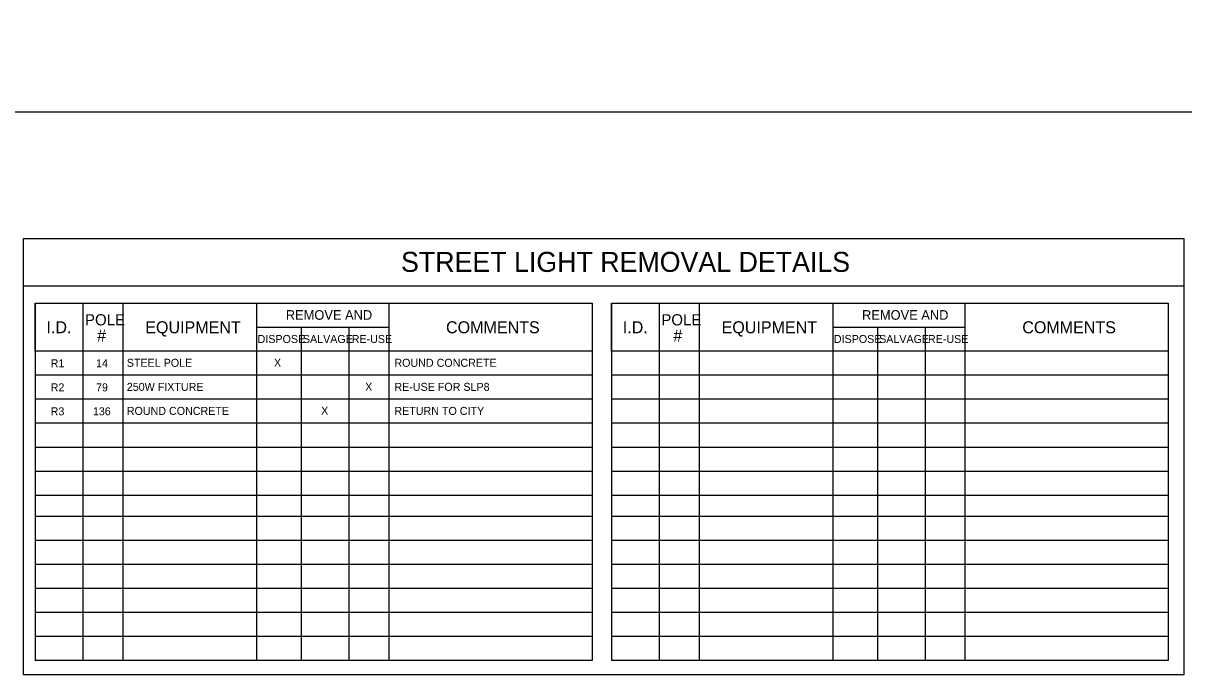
# Model space of a CAD drawing. Extents: x 602909 to 603631, y 4846273 to 4846729.
# Drawn here: x 603054.8 to 603194.8, y 4846272.8 to 4846351.3 of the extents above; entities that cross this region are included whole.
import ezdxf

# ---------------------------------------------------------------- set-up
doc = ezdxf.new("R2010")
doc.units = 0
for name, color, linetype in [('-PRINT FULLSIZE', 7, 'Continuous'), ('ENG_BORDER', 7, 'Continuous'), ('ENG_TITLEBLOCK', 7, 'Continuous'), ('ENG_TX_TITLEBLOCK', 7, 'Continuous'), ('SL - Border Text', 7, 'Continuous')]:
    doc.layers.add(name, color=color, linetype=linetype)

msp = doc.modelspace()

# ---------------------------------------------------------------- linework, layer by layer
at = {"layer": '-PRINT FULLSIZE'}
msp.add_lwpolyline([(602930, 4846340.65), (603377.03, 4846340.65), (603377.03, 4846645.65), (602930, 4846645.65)], close=True, dxfattribs=at)
at = {"layer": 'ENG_BORDER'}
msp.add_line((603054.8, 4846319.66), (603194.76, 4846319.66), dxfattribs=at)
msp.add_lwpolyline([(603054.8, 4846325.39), (603194.76, 4846325.39), (603194.76, 4846272.8), (603054.8, 4846272.8)], close=True, dxfattribs=at)
at = {"layer": 'ENG_TITLEBLOCK'}
for p, q in [((603056.19, 4846317.59), (603056.19, 4846274.5)), ((603061.96, 4846317.59), (603061.96, 4846274.5)), ((603066.79, 4846317.59), (603066.79, 4846274.5)), ((603082.92, 4846317.59), (603082.92, 4846274.5)), ((603098.85, 4846317.59), (603098.85, 4846274.5)), ((603123.38, 4846317.59), (603123.38, 4846274.5)), ((603125.71, 4846317.59), (603125.71, 4846274.5)), ((603131.47, 4846317.59), (603131.47, 4846274.5)), ((603136.31, 4846317.59), (603136.31, 4846274.5)), ((603152.43, 4846317.59), (603152.43, 4846274.5)), ((603168.36, 4846317.59), (603168.36, 4846274.5)), ((603192.89, 4846317.59), (603192.89, 4846274.5)), ((603082.92, 4846314.7), (603098.85, 4846314.7)), ((603088.31, 4846314.7), (603088.31, 4846274.5)), ((603094.05, 4846314.7), (603094.05, 4846274.5)), ((603152.43, 4846314.7), (603168.36, 4846314.7)), ((603157.82, 4846314.7), (603157.82, 4846274.5)), ((603163.56, 4846314.7), (603163.56, 4846274.5)), ((603123.38, 4846308.9), (603056.19, 4846308.9)), ((603192.89, 4846308.9), (603125.71, 4846308.9)), ((603123.38, 4846306.01), (603056.19, 4846306.01)), ((603192.89, 4846306.01), (603125.71, 4846306.01)), ((603123.38, 4846303.11), (603056.19, 4846303.11)), ((603192.89, 4846303.11), (603125.71, 4846303.11)), ((603123.38, 4846300.21), (603056.19, 4846300.21)), ((603192.89, 4846300.21), (603125.71, 4846300.21)), ((603123.38, 4846297.32), (603056.19, 4846297.32)), ((603192.89, 4846297.32), (603125.71, 4846297.32)), ((603123.38, 4846294.42), (603056.19, 4846294.42)), ((603192.89, 4846294.42), (603125.71, 4846294.42)), ((603123.38, 4846291.88), (603056.19, 4846291.88)), ((603192.89, 4846291.88), (603125.71, 4846291.88)), ((603123.38, 4846288.98), (603056.19, 4846288.98)), ((603192.89, 4846288.98), (603125.71, 4846288.98)), ((603123.38, 4846286.09), (603056.19, 4846286.09)), ((603192.89, 4846286.09), (603125.71, 4846286.09)), ((603123.38, 4846283.19), (603056.19, 4846283.19)), ((603192.89, 4846283.19), (603125.71, 4846283.19)), ((603123.38, 4846280.29), (603056.19, 4846280.29)), ((603192.89, 4846280.29), (603125.71, 4846280.29)), ((603123.38, 4846277.4), (603056.19, 4846277.4)), ((603192.89, 4846277.4), (603125.71, 4846277.4)), ((603123.38, 4846274.5), (603056.19, 4846274.5)), ((603192.89, 4846274.5), (603125.71, 4846274.5))]:
    msp.add_line(p, q, dxfattribs=at)
for points in [[(603056.19, 4846317.59), (603123.38, 4846317.59), (603123.38, 4846311.8), (603056.19, 4846311.8)], [(603125.71, 4846317.59), (603192.89, 4846317.59), (603192.89, 4846311.8), (603125.71, 4846311.8)]]:
    msp.add_lwpolyline(points, close=True, dxfattribs=at)
at = {"layer": 'SL - Border Text'}
for p, q in [((603056.19, 4846317.59), (603123.38, 4846317.59)), ((603061.96, 4846317.59), (603061.96, 4846317.59)), ((603125.71, 4846317.59), (603192.89, 4846317.59)), ((603082.92, 4846314.7), (603098.85, 4846314.7)), ((603152.43, 4846314.7), (603168.36, 4846314.7)), ((603123.38, 4846311.8), (603056.19, 4846311.8)), ((603192.89, 4846311.8), (603125.71, 4846311.8))]:
    msp.add_line(p, q, dxfattribs=at)

# ---------------------------------------------------------------- texts
at = {"layer": 'ENG_TX_TITLEBLOCK'}
for s, height, rotation, p in [('STREET LIGHT REMOVAL DETAILS', 2.4137, 360, (603100.34, 4846321.36)), ('POLE', 1.352, 359.9999, (603062.22, 4846314.91)), ('REMOVE AND', 1.159, 359.9999, (603086.44, 4846315.59)), ('POLE', 1.352, 359.9999, (603131.74, 4846314.91)), ('REMOVE AND', 1.159, 359.9999, (603155.95, 4846315.59)), ('I.D.', 1.448, 359.9999, (603057.57, 4846313.96)), ('EQUIPMENT', 1.448, 359.9999, (603069.49, 4846313.96)), ('COMMENTS', 1.448, 359.9999, (603105.77, 4846313.96)), ('I.D.', 1.448, 359.9999, (603127.09, 4846313.96)), ('EQUIPMENT', 1.448, 359.9999, (603139.01, 4846313.96)), ('COMMENTS', 1.448, 359.9999, (603175.28, 4846313.96)), ('#', 1.45, 359.9999, (603063.68, 4846312.97)), ('DISPOSE', 0.965, 359.9999, (603083.04, 4846312.79)), ('SALVAGE', 0.965, 359.9999, (603088.5, 4846312.79)), ('RE-USE', 0.965, 359.9999, (603094.39, 4846312.79)), ('#', 1.45, 359.9999, (603133.19, 4846312.97)), ('DISPOSE', 0.965, 359.9999, (603152.55, 4846312.79)), ('SALVAGE', 0.965, 359.9999, (603158.01, 4846312.79)), ('RE-USE', 0.965, 359.9999, (603163.9, 4846312.79)), ('R1', 0.965, 359.9999, (603058.08, 4846309.86)), ('14', 0.965, 359.9999, (603063.55, 4846309.86)), ('STEEL POLE', 0.965, 359.9999, (603067.26, 4846309.92)), ('X', 0.965, 359.9999, (603085.01, 4846309.94)), ('ROUND CONCRETE', 0.9655, 359.9999, (603099.54, 4846309.92)), ('R2', 0.965, 359.9999, (603058.08, 4846306.96)), ('79', 0.965, 359.9999, (603063.55, 4846306.96)), ('250W FIXTURE', 0.9655, 359.9999, (603067.26, 4846307.02)), ('X', 0.965, 359.9999, (603096.01, 4846307.04)), ('RE-USE FOR SLP8', 0.9655, 359.9999, (603099.54, 4846307.02)), ('R3', 0.965, 359.9999, (603058.08, 4846304.07)), ('136', 0.965, 359.9999, (603063.17, 4846304.07)), ('ROUND CONCRETE', 0.9655, 359.9999, (603067.26, 4846304.12)), ('X', 0.965, 359.9999, (603090.7, 4846304.15)), ('RETURN TO CITY', 0.9655, 359.9999, (603099.54, 4846304.12))]:
    msp.add_text(s, height=height, rotation=rotation, dxfattribs=at).set_placement(p)

doc.saveas('drawing.dxf')
